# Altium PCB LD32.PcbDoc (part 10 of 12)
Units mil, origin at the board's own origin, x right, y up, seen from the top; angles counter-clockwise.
Board outline 7007.87 x 4368.85 mil, 12 copper layers (Top Layer, Int1 (GND), Int2 (AVDD), Int3 (DVDD), Int4 (GND), Int5 (ST), Int6 (SB), Int8 (AGND), Int7 (AVCC), Int9 (VCCA), Int10 (GND), Bottom Layer), stack 60.136 mil thick; 1165 components, 667 nets, 3910 pads, 2570 vias.
Unrouted connection lines stored in the file: 14.
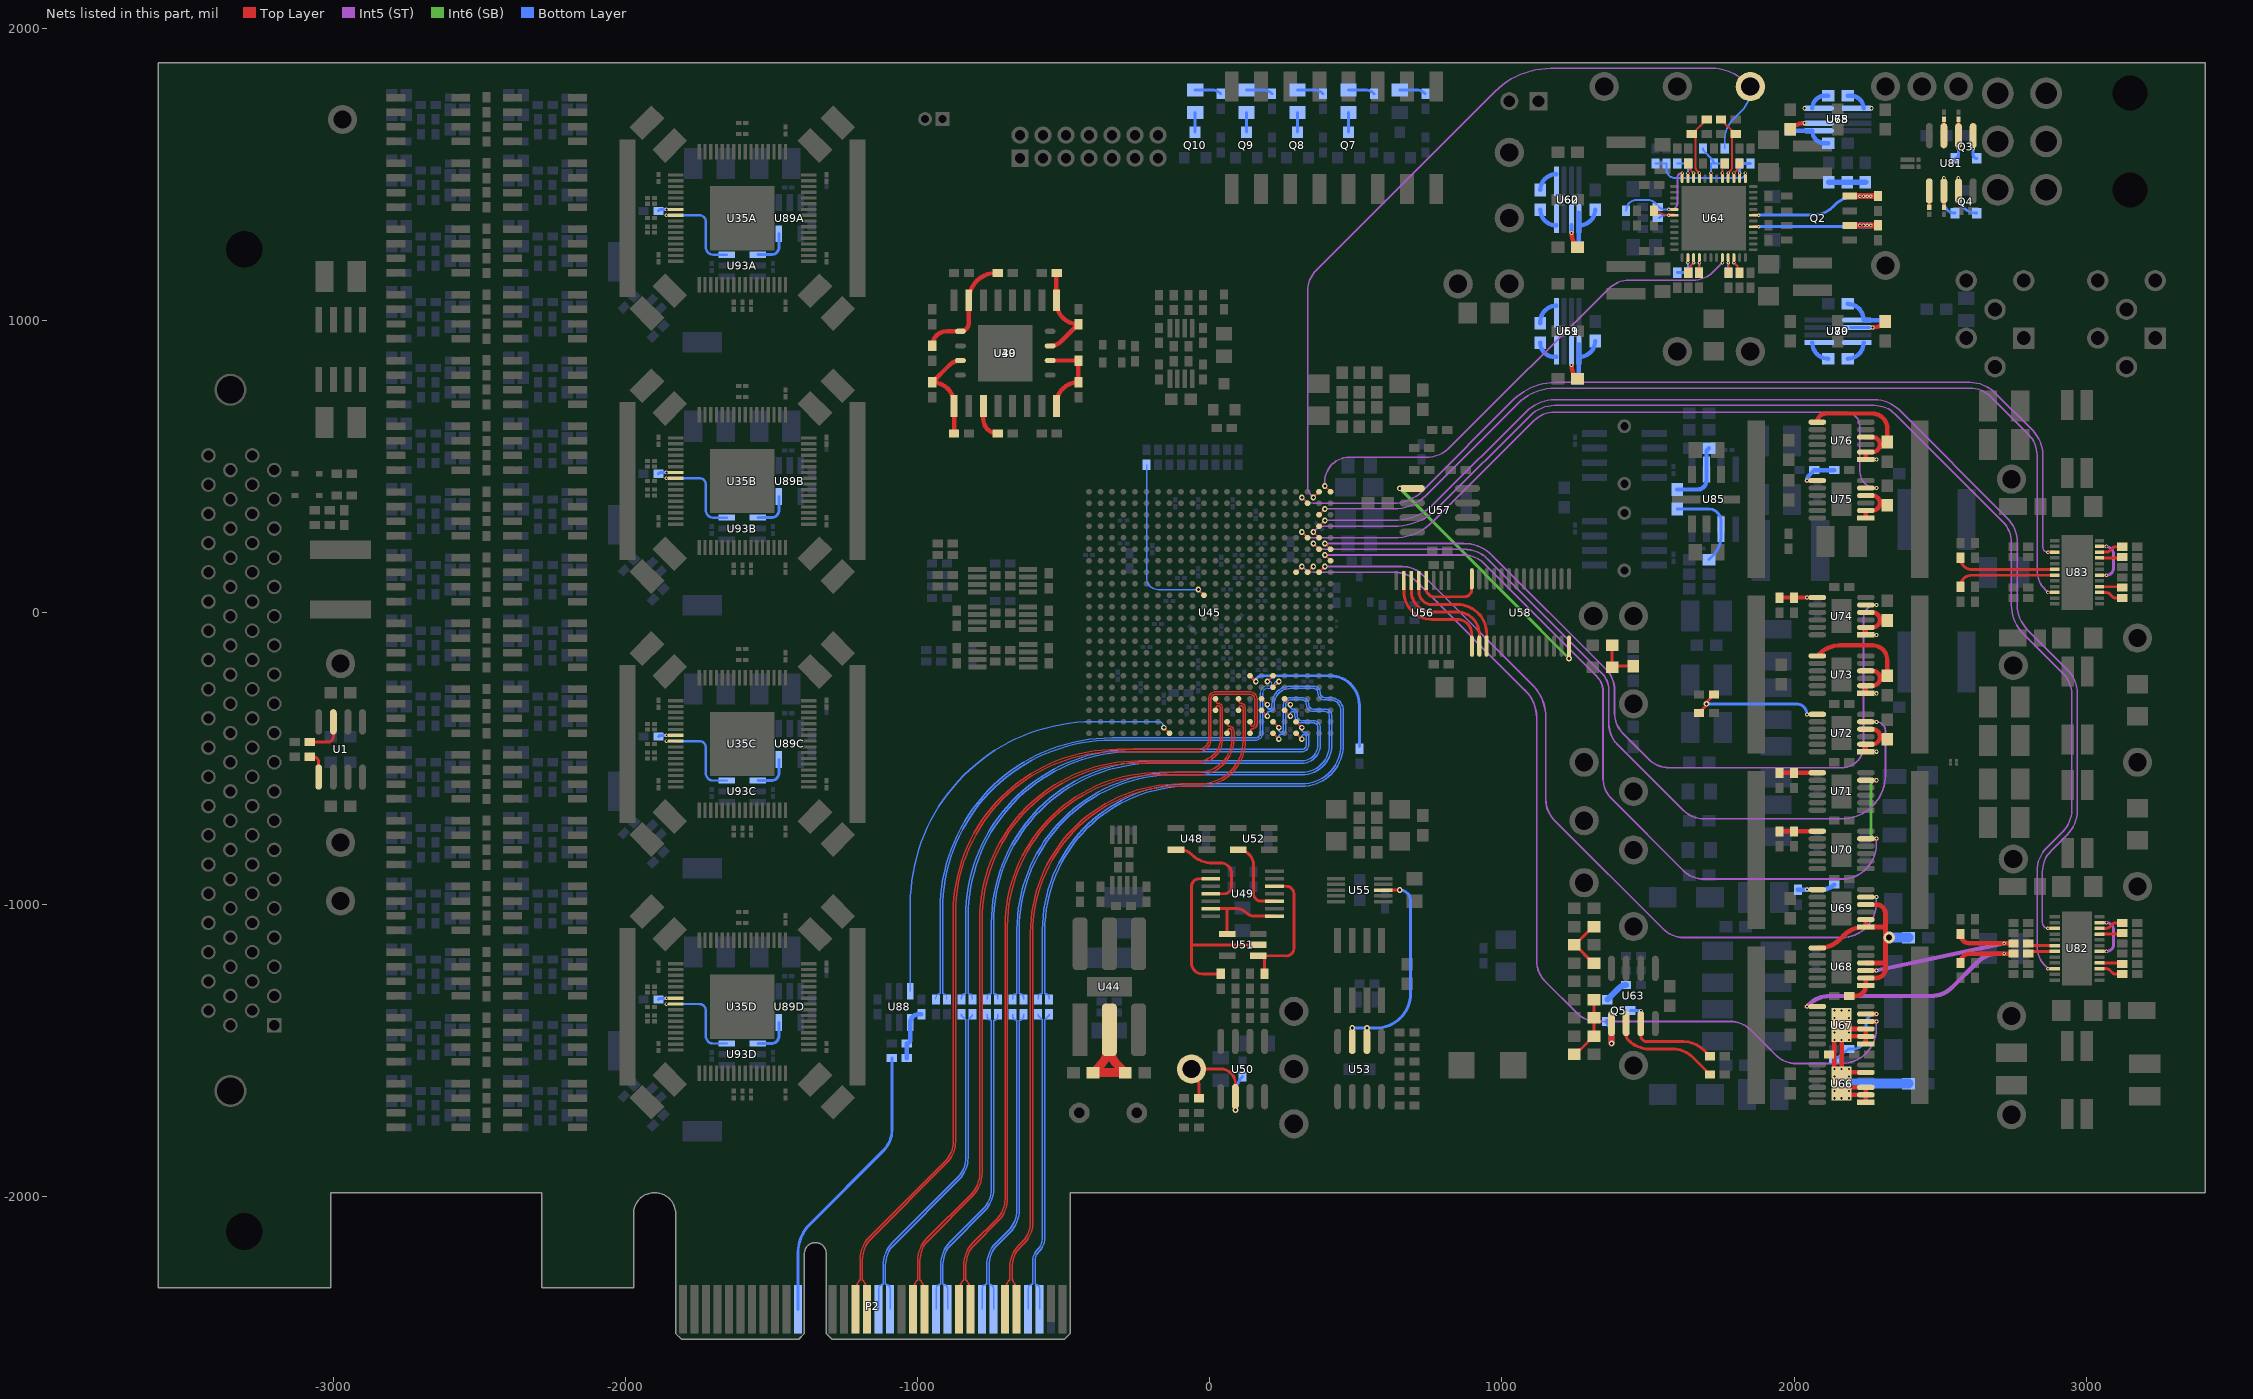
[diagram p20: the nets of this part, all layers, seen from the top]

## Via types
v1: diameter 12, hole 6, Top Layer to Bottom Layer, tented both sides, 1500 vias
v2: diameter 19, hole 10, Top Layer to Bottom Layer, tented both sides, 404 vias
v3: diameter 20, hole 10, Top Layer to Bottom Layer, tented both sides, 337 vias
v4: diameter 14, hole 7, Top Layer to Bottom Layer, tented both sides, 212 vias
v5: diameter 30, hole 15, Top Layer to Bottom Layer, tented both sides, 37 vias
v6: diameter 19.68, hole 7.87, Top Layer to Bottom Layer, 25 vias
v7: diameter 40, hole 20, Top Layer to Bottom Layer, tented both sides, 16 vias
v8: diameter 19.02, hole 10, Top Layer to Bottom Layer, tented both sides, 10 vias
v9: diameter 40, hole 20, Top Layer to Bottom Layer, 9 vias
v10: diameter 60, hole 40, Top Layer to Bottom Layer, 5 vias
v11: diameter 25, hole 13, Top Layer to Bottom Layer, 4 vias
v12: diameter 50, hole 25, Top Layer to Bottom Layer, tented both sides, 4 vias
v13: diameter 35, hole 20, Top Layer to Bottom Layer, 2 vias
v14: diameter 50, hole 25, Top Layer to Bottom Layer, 2 vias
v15: diameter 63, hole 45, Top Layer to Bottom Layer, 1 vias
v16: diameter 14.02, hole 7.01, Top Layer to Bottom Layer, tented both sides, 1 vias
v17: diameter 60, hole 40, Top Layer to Bottom Layer, tented both sides, 1 vias

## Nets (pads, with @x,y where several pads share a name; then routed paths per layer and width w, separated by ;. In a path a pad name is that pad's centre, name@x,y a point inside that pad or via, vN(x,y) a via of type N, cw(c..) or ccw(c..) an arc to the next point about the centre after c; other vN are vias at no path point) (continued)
NetDS2_2: DS2.2 R281.2 | length 90.9
  Bottom Layer w10: DS2.2@650,1788.39 706.61,1788.39 cw(c706.61,1744.7) R281.2@737.5,1775.59
NetDS3_1: DS3.1 Q7.3 | length 67.3
  Bottom Layer w10: Q7.3@475,1644.29 DS3.1@475,1711.61
NetDS3_2: DS3.2 R286.2 | length 90.9
  Bottom Layer w10: DS3.2@475,1788.39 531.61,1788.39 cw(c531.61,1744.7) R286.2@562.5,1775.59
NetDS4_1: DS4.1 Q8.3 | length 67.3
  Bottom Layer w10: Q8.3@300,1644.29 DS4.1@300,1711.61
NetDS4_2: DS4.2 R289.2 | length 90.9
  Bottom Layer w10: DS4.2@300,1788.39 356.61,1788.39 cw(c356.61,1744.7) R289.2@387.5,1775.59
NetDS5_1: DS5.1 Q9.3 | length 67.3
  Bottom Layer w10: Q9.3@125,1644.29 DS5.1@125,1711.61
NetDS5_2: DS5.2 R291.2 | length 90.9
  Bottom Layer w10: DS5.2@125,1788.39 181.61,1788.39 cw(c181.61,1744.7) R291.2@212.5,1775.59
NetDS6_1: DS6.1 Q10.3 | length 67.3
  Bottom Layer w10: Q10.3@-50,1644.29 DS6.1@-50,1711.61
NetDS6_2: DS6.2 R296.2 | length 90.9
  Bottom Layer w10: DS6.2@-50,1788.39 6.61,1788.39 cw(c6.61,1744.7) R296.2@37.5,1775.59
NetQ2_2: Q2.2 R187.1 U64.29 | length 513.9
  Top Layer w10: U64.29@1859.84,1320.47 v1(1878.54,1320.47)
  Top Layer w20: Q2.2@2190.16,1325 v1(2225,1325) v1(2237.5,1325) v1(2250,1325) v1(2262.5,1325) 2286.07,1325 ccw(c2286.07,1327.02) R187.1@2287.5,1325.59
  Bottom Layer w10: v1(1878.54,1320.47) 2226.57,1320.47 ccw(c2226.57,1335.93) v1(2237.5,1325)
  Bottom Layer w20: v1(2225,1325) v1(2237.5,1325) v1(2250,1325) v1(2262.5,1325)
NetQ2_4: Q2.4 R188.1 U64.31 | length 518.5
  Top Layer w10: U64.31@1859.84,1359.84 v1(1878.54,1359.84)
  Top Layer w20: Q2.4@2190.16,1425 v1(2225,1425) v1(2237.5,1425) v1(2250,1425) v1(2262.5,1425) 2286.07,1425 ccw(c2286.07,1427.02) R188.1@2287.5,1425.59
  Bottom Layer w10: v1(1878.54,1359.84) 2062.61,1359.84 ccw(c2062.61,1459.84) 2133.32,1389.13 2139.9,1395.71 cw(c2210.61,1325) 2210.61,1425 v1(2225,1425)
  Bottom Layer w20: v1(2225,1425) v1(2237.5,1425) v1(2250,1425) v1(2262.5,1425)
NetQ3_1: Q3.1 U81.1 | length 84.7
  Top Layer w10: v1(2612.5,1587.5) U81.1@2612.5,1631.99
  Bottom Layer w10: v1(2612.5,1587.5) 2612.5,1566.78 ccw(c2624.9,1566.78) Q3.1@2624.9,1554.38
NetQ3_2: Q3.2 R200.1 U81.2 | length 140.8
  Top Layer w10: v1(2562.5,1587.5) U81.2@2562.5,1631.99 R200.1@2562.5,1688.06
  Bottom Layer w10: Q3.2@2550.1,1554.38 ccw(c2550.1,1566.78) 2562.5,1566.78 v1(2562.5,1587.5)
NetQ4_1: Q4.1 U81.7 | length 200.7
  Top Layer w10: U81.7@2562.5,1443.01 v1(2562.5,1487.5)
  Bottom Layer w10: v1(2562.5,1487.5) 2562.5,1429.28 ccw(c2624.9,1429.28) Q4.1@2624.9,1366.88
NetQ4_2: Q4.2 R223.2 U81.6 | length 242.6
  Top Layer w10: R223.2@2512.5,1386.94 U81.6@2512.5,1443.01 v1(2512.5,1487.5)
  Bottom Layer w10: v1(2512.5,1487.5) 2512.5,1404.48 ccw(c2550.1,1404.48) Q4.2@2550.1,1366.88
NetQ5_1: Q5.1 U63.1 | length 147
  Top Layer w20: v8(1375,-1475) U63.1@1375,-1406.99
  Bottom Layer w20: Q5.1@1360.63,-1399.9 cw(c1325.94,-1434.59) 1375,-1434.59 v8(1375,-1475)
NetQ5_2: Q5.2 R274.1 | length 83.1
  Bottom Layer w20: Q5.2@1360.63,-1325.1 1401.05,-1284.67 cw(c1424.41,-1308.03) R274.1@1424.41,-1275
NetQ5_3: Q5.3 R247.2 U63.3 | length 342.4
  Top Layer w10: U63.3@1475,-1406.99 1475,-1450 ccw(c1490.09,-1450) 1479.42,-1460.67 1481.25,-1462.5 ccw(c1496.34,-1447.41) 1496.34,-1468.75 1620.49,-1468.75 cw(c1620.49,-1568.75) 1691.2,-1498.04 R247.2@1711.91,-1518.75
  Bottom Layer w10: Q5.3@1439.37,-1362.5 v1(1475.59,-1362.5)
NetR1_1: R1.1 U1.5 | length 92.1
  Top Layer w10: R1.1@-3080.66,-493.75 -3068.75,-493.75 cw(c-3068.75,-512.5) -3050,-512.5 U1.5@-3050,-563.24
NetR2_1: R2.1 U1.3 | length 142.2
  Top Layer w10: R2.1@-3080.66,-443.75 -3018.61,-443.75 ccw(c-3018.61,-425.14) -3000,-425.14 U1.3@-3000,-374.26
NetR67_1: R67.1 R72.1 U39.1 U40.7 | length 344
  Top Layer w15: R72.1@-875.59,612.5 -875,612.5 U39.1@-875,706.4 -875,713.09 ccw(c-950,713.09) R67.1@-950,788.09 -891.18,846.91 cw(c-853.54,809.28) U40.7@-853.54,862.5
NetR68_1: R68.1 R83.1 U39.15 U40.5 | length 400.1
  Top Layer w15: R68.1@-950,913.09 cw(c-900.59,913.09) -900.59,962.5 U40.5@-853.54,962.5 ccw(c-853.54,991.04) -825,991.04 U39.15@-825,1068.6 cw(c-731.1,1068.6) -731.1,1162.5 R83.1@-725.59,1162.5
NetR82_1: R82.1 U39.3 | length 122.1
  Top Layer w15: U39.3@-775,706.4 -775,661.91 ccw(c-725.59,661.91) R82.1@-725.59,612.5
NetR84_1: R84.1 R90.1 U39.9 U40.3 | length 344
  Top Layer w15: U40.3@-546.46,912.5 ccw(c-546.46,965.72) -508.82,928.09 R90.1@-450,986.91 cw(c-450,1061.91) -525,1061.91 U39.9@-525,1068.6 -525,1162.5 R84.1@-524.41,1162.5
NetR87_1: R87.1 R94.1 U44.2 | length 344.3
  Top Layer w30: R87.1@-399.61,-1574.8 -375.75,-1550.94 ccw(c-446.46,-1480.23) -346.46,-1480.23 -346.46,-1476.29 ccw(c-246.46,-1476.29) -317.17,-1547.01 R94.1@-289.37,-1574.8 R87.1@-399.61,-1574.8
NetR88_1: R88.1 R89.1 U39.8 U40.2 | length 295
  Top Layer w15: U40.2@-546.46,862.5 -450.59,862.5 R89.1@-450,861.91 R88.1@-450,788.09 ccw(c-450,713.09) -525,713.09 U39.8@-525,706.4
NetR102_1: R102.1 R292.2 TP4.1 U50.6 | length 451
  Top Layer w10: R102.1@-36.91,-1662.5 -36.91,-1624.28 ccw(c-124.28,-1624.28) TP4.1@-62.5,-1562.5 37.5,-1562.5 cw(c37.5,-1612.5) 87.5,-1612.5 U50.6@87.5,-1656.99
  Bottom Layer w10: v3(87.5,-1702.5) 87.5,-1648.45 cw(c172.86,-1648.45) R292.2@112.5,-1588.09
NetR108_1: R108.1 U49.9 U51.2 | length 692.4
  Top Layer w10: U49.9@3.25,-911.32 -36.32,-911.32 ccw(c-36.32,-937.5) -62.5,-937.5 -62.5,-1137.5 ; R108.1@37.5,-1236.91 -25.59,-1236.91 cw(c-25.59,-1200) -62.5,-1200 -62.5,-1137.5 ; U51.2@165.65,-1137.5 -62.5,-1137.5
NetR113_1: R113.1 U49.5 U51.1 | length 466.1
  Top Layer w10: U51.1@165.65,-1174.9 U51.1@187.5,-1174.9 ; R113.1@187.5,-1236.91 U51.1@187.5,-1174.9 ; U49.5@221.75,-936.91 261.91,-936.91 cw(c261.91,-962.5) 287.5,-962.5 287.5,-1150 cw(c262.5,-1150) 262.5,-1175 262.5,-1174.9 U51.1@187.5,-1174.9
NetR122_1: R122.1 U59.6 U61.6 | length 52.6
  Top Layer w15: v4(1237.8,846.76) ccw(c1300.78,846.76) 1256.24,802.23 R122.1@1258.46,800
NetR123_2: R123.2 R124.1 U59.5 U61.5 | length 206.8
  Bottom Layer w15: R123.2@1258.46,800 ccw(c1246.58,811.88) 1263.39,811.88 U61.5@1263.39,919.17 ; U59.5@1263.39,874.9 1264.62,874.9 ccw(c1264.62,929.04) R124.1@1318.75,929.04
NetR125_1: R125.1 R127.2 U60.5 U62.5 | length 206.8
  Bottom Layer w15: R127.2@1258.46,1250 ccw(c1246.58,1261.88) 1263.39,1261.88 U62.5@1263.39,1369.17 ; U60.5@1263.39,1324.9 1264.62,1324.9 ccw(c1264.62,1379.04) R125.1@1318.75,1379.04
NetR126_1: R126.1 U60.6 U62.6 | length 80.5
  Top Layer w15: v4(1237.8,1299.5) ccw(c1307.4,1299.5) 1258.18,1250.28 R126.1@1258.46,1250
  Bottom Layer w15: v4(1237.8,1299.5) U60.6@1237.8,1324.9
NetR130_1: R130.1 R131.1 R136.2 R140.1 | length 217
  Top Layer w10: R140.1@1248.75,-1510 1260.94,-1497.81 1266.9,-1497.81 1298.06,-1466.65 1298.06,-1464.69 1312.75,-1450 R136.2@1314.71,-1450 R130.1@1314.71,-1387.5 R131.1@1314.71,-1325
NetR133_1: R133.1 R134.2 R135.1 | length 180.5
  Top Layer w10: R134.2@1247.79,-1137.5 ccw(c1247.79,-1133.32) 1250.74,-1136.28 1310.11,-1076.91 cw(c1314.71,-1081.52) R135.1@1314.71,-1075 ; R134.2@1251.57,-1139.07 1310.94,-1198.44 ccw(c1314.71,-1194.65) R133.1@1314.71,-1200
NetR137_1: R137.1 R138.2 R139.1 | length 148.9
  Top Layer w10: R139.1@1377.21,-112.5 R137.1@1377.21,-187.5 cw(c1386.96,-197.24) 1386.96,-183.46 R138.2@1450,-183.46
NetR141_1: R141.1 U59.8 U61.8 | length 82.7
  Bottom Layer w15: R141.1@1131.25,922.79 ccw(c1179.13,922.79) 1179.13,874.9 U59.8@1186.61,874.9
NetR141_2: R141.2 U59.1 U61.1 | length 92
  Bottom Layer w15: R141.2@1131.25,989.71 1131.25,994.73 cw(c1186.61,994.73) U59.1@1186.61,1050.1
NetR142_1: R142.1 U60.8 U62.8 | length 86.3
  Bottom Layer w15: R142.1@1131.25,1379.04 ccw(c1185.38,1379.04) 1185.38,1324.9 U60.8@1186.61,1324.9
NetR142_2: R142.2 U60.1 U62.1 | length 86.3
  Bottom Layer w15: R142.2@1131.25,1445.96 cw(c1185.38,1445.96) 1185.38,1500.1 U60.1@1186.61,1500.1
NetR143_2: R143.2 U63.2 | length 381.2
  Top Layer w10: U63.2@1425,-1450 U63.2@1425,-1447.13 ; U63.2@1425,-1406.99 U63.2@1425,-1447.13 ; R143.2@1711.91,-1581.25 1653.7,-1523.04 ccw(c1582.99,-1593.75) 1582.99,-1493.75 1504.04,-1493.75 cw(c1504.04,-1393.75) 1433.33,-1464.46 1431.37,-1462.5 cw(c1446.74,-1447.13) U63.2@1425,-1447.13
NetR144_1: R144.1 R269.1 U64.6 | length 112.6
  Top Layer w7: R144.1@1520,1383.46 1524.26,1379.2 ccw(c1571,1425.94) v1(1571,1359.84)
  Top Layer w10: v1(1571,1359.84) U64.6@1590.16,1359.84
  Bottom Layer w7: R269.1@1538.09,1350 cw(c1561.85,1326.24) 1561.85,1359.84 v1(1571,1359.84)
NetR145_2: R145.2 U64.15 | length 58.1
  Top Layer w7: R145.2@1637.5,1163.09 cw(c1675.33,1163.09) 1648.58,1189.84 v1(1656.1,1197.36)
  Top Layer w10: v1(1656.1,1197.36) U64.15@1656.1,1215.16
NetR146_2: R146.2 U64.46 | length 58.3
  Top Layer w7: R146.2@1637.5,1536.91 ccw(c1671.95,1536.91) 1647.59,1512.55 v1(1656.1,1504.04)
  Top Layer w10: U64.46@1656.1,1484.84 v1(1656.1,1504.04)
NetR147_1: R147.1 R148.1 U64.45 | length 229.1
  Top Layer w7: R148.1@1649.41,1637.5 ccw(c1649.41,1640.35) 1651.42,1638.33 R147.1@1700.59,1687.5 ; R148.1@1662.5,1637.5 1662.5,1525 ccw(c1681.03,1525) 1667.93,1511.89 v1(1675.79,1504.04)
  Top Layer w10: U64.45@1675.79,1484.84 v1(1675.79,1504.04)
NetR149_1: R149.1 R150.2 U72.7 | length 482.5
  Top Layer w10: R149.1@1674.41,-343.75 1696,-322.16 ccw(c1686.34,-312.5) v3(1700,-312.5) cw(c1713.66,-312.5) 1704,-302.84 R150.2@1725.59,-281.25 ; v4(2043.75,-348.52) U72.7@2079.44,-348.52
  Bottom Layer w10: v3(1700,-312.5) 2007.73,-312.5 cw(c2007.73,-348.52) v4(2043.75,-348.52)
NetR151_1: R151.1 R152.2 U75.7 | length 148.8
  Top Layer w15: v4(2043.75,451.48) U75.7@2079.44,451.48
  Bottom Layer w15: v4(2043.75,451.48) cw(c2068.94,451.48) 2051.12,469.28 R152.2@2069.34,487.5 R151.1@2136.91,487.5
NetR153_1: R153.1 R261.1 U64.16 | length 87
  Top Layer w7: R153.1@1675,1163.09 1675,1214.37 cw(c1675.79,1214.37) U64.16@1675.79,1215.16
  Bottom Layer w7: R261.1@1675,1163.09 ccw(c1673.1,1164.99) 1675.79,1164.99 v1(1675.79,1197.36)
NetR154_1: R154.1 R155.1 U64.40 | length 229.1
  Top Layer w7: R155.1@1749.41,1687.5 1798.57,1638.34 ccw(c1800.59,1640.35) R154.1@1800.59,1637.5 ; v1(1774.21,1504.04) 1782.07,1511.89 ccw(c1768.97,1525) 1787.5,1525 R154.1@1787.5,1637.5
  Top Layer w10: U64.40@1774.21,1484.84 v1(1774.21,1504.04)
NetR156_1: R156.1 U64.41 | length 54.2
  Top Layer w7: v1(1754.53,1504.04) 1754.53,1517.66 cw(c1781.75,1517.66) R156.1@1762.5,1536.91
  Top Layer w10: U64.41@1754.53,1484.84 v1(1754.53,1504.04)
NetR157_1: R157.1 R251.1 U64.21 | length 87
  Top Layer w7: U64.21@1774.21,1215.16 cw(c1774.21,1214.37) 1775,1214.37 R157.1@1775,1163.09
  Bottom Layer w7: v1(1774.21,1197.36) 1774.21,1164.99 ccw(c1776.9,1164.99) R251.1@1775,1163.09
NetR158_2: R158.2 U64.22 | length 58.1
  Top Layer w7: v1(1793.9,1197.36) 1801.42,1189.84 cw(c1774.67,1163.09) R158.2@1812.5,1163.09
  Top Layer w10: v1(1793.9,1197.36) U64.22@1793.9,1215.16
NetR159_2: R159.2 U64.39 | length 58.3
  Top Layer w7: v1(1793.9,1504.04) 1802.41,1512.55 ; 1802.42,1512.56 ccw(c1778.05,1536.91) R159.2@1812.5,1536.91
  Top Layer w10: U64.39@1793.9,1484.84 v1(1793.9,1504.04)
NetR161_1: R161.1 U65.6 U78.6 | length 53.8
  Top Layer w15: R161.1@1987.5,1654.04 1988.76,1655.3 cw(c2035.61,1608.45) v4(2035.61,1674.7)
NetR162_1: R162.1 R170.2 U70.7 | length 129.9
  Top Layer w16: R162.1@1950,-749.41 cw(c1950.89,-749.41) 1950.89,-748.52 U70.7@2079.44,-748.52
NetR163_1: R163.1 R171.2 U71.7 | length 129.9
  Top Layer w16: R163.1@1950,-549.41 cw(c1950.89,-549.41) 1950.89,-548.52 U71.7@2079.44,-548.52
NetR164_2: R164.2 R172.1 U74.7 | length 129.7
  Top Layer w15: R164.2@1950,50.59 cw(c1952.14,48.45) 1952.14,51.48 v4(2043.75,51.48) U74.7@2079.44,51.48
NetR169_2: R169.2 R176.1 U65.5 U78.5 | length 156.8
  Bottom Layer w15: R169.2@1987.5,1654.04 ccw(c1992.42,1654.04) 1992.42,1649.11 U65.5@2062.4,1649.11 2062.4,1647.88 ccw(c2104.04,1647.88) 2104.04,1606.25 R176.1@2116.54,1606.25
NetR174_1: R174.1 R225.1 U66.1 U66.2 U66.3 U66.5 U66.13 U67.1 U67.2 U67.3 U67.13 | length 1001.9
  Top Layer w15: v4(2137.5,-1562.2) v4(2137.5,-1462.5) ; v4(2162.5,-1562.5) ccw(c2174.11,-1562.5) 2174.11,-1574.11 U66.5@2245.56,-1574.11
  Top Layer w16: v4(2162.5,-1662.5) 2162.5,-1650.89 U66.2@2245.56,-1650.89 ; v9(2162.5,-1612.5) 2162.5,-1625.3 U66.3@2245.56,-1625.3 U66.2@2245.56,-1650.89 ; v4(2162.5,-1562.5) v4(2162.5,-1462.5) 2162.5,-1450.89 U67.2@2245.56,-1450.89 ; v9(2162.5,-1412.5) 2162.5,-1425.3 U67.3@2245.56,-1425.3 U67.2@2245.56,-1450.89 ; U66.1@2245.56,-1676.48 U66.2@2245.56,-1650.89 ; U67.1@2245.56,-1476.48 U67.2@2245.56,-1450.89
  Bottom Layer w35: v9(2162.5,-1612.5) R225.1@2391.54,-1612.5
  other v4: 2137.5,-1662.5 2187.5,-1662.5 2137.5,-1637.5 2187.5,-1637.5 2137.5,-1587.5 2187.5,-1587.5 2187.5,-1562.5 2187.5,-1462.5 2137.5,-1437.5 2187.5,-1437.5 2137.5,-1387.5 2187.5,-1387.5 2137.5,-1362.5 2162.5,-1362.5 2187.5,-1362.5
NetR175_1: R175.1 U65.8 U78.8 | length 79.8
  Bottom Layer w15: U65.8@2062.4,1727.12 U65.8@2062.4,1725.89 cw(c2105.27,1725.89) 2105.27,1768.75 R175.1@2116.54,1768.75
  other v4: 2035.61,1725.89
NetR175_2: R175.2 U65.1 U78.1 | length 79.8
  Bottom Layer w10: U65.1@2237.6,1725.89 U65.1@2237.6,1727.12
  Bottom Layer w15: R175.2@2183.46,1768.75 2194.73,1768.75 cw(c2194.73,1725.89) U65.1@2237.6,1725.89
  other v4: 2264.86,1725.89
NetR180_2: R180.2 R226.1 U68.1 U68.2 U68.4 U68.7 U69.1 U69.2 U69.4 | length 875.2
  Top Layer w16: U68.7@2079.44,-1148.52 2085.06,-1148.52 ccw(c2085.06,-1048.52) 2155.77,-1119.23 2169.23,-1105.77 cw(c2239.95,-1176.48) 2239.95,-1076.48 U69.1@2245.56,-1076.48 ; R180.2@2188.09,-1312.5 2209.54,-1312.5 ccw(c2209.54,-1276.48) U68.1@2245.56,-1276.48 U68.2@2245.56,-1250.89 2281.25,-1250.89 2281.25,-1250.59 ccw(c2281.25,-1219.34) 2312.5,-1219.34 2312.5,-1199.7 ; U68.4@2245.56,-1199.7 2312.5,-1199.7 ; U69.2@2245.56,-1050.89 U69.1@2245.56,-1076.48 ; U69.4@2245.56,-999.7 2281.25,-999.7 cw(c2281.25,-1030.95) 2312.5,-1030.95 2312.5,-1076.48 ; U69.1@2245.56,-1076.48 2312.5,-1076.48 ; 2312.5,-1199.7 2312.5,-1076.48
  Bottom Layer w35: v7(2325,-1112.5) R226.1@2391.54,-1112.5
NetR184_1: R184.1 U79.8 U80.8 | length 86.3
  Bottom Layer w15: R184.1@2183.46,868.75 ccw(c2183.46,922.88) 2237.6,922.88 U79.8@2237.6,924.11
NetR184_2: R184.2 U79.1 U80.1 | length 86.3
  Bottom Layer w15: U79.1@2062.4,924.11 2062.4,922.88 ccw(c2116.54,922.88) R184.2@2116.54,868.75
NetR185_1: R185.1 R195.2 U79.5 U80.5 | length 171.7
  Bottom Layer w15: R185.1@2183.46,1056.25 cw(c2183.46,1002.12) 2237.6,1002.12 U79.5@2237.6,1000.89 2307.58,1000.89 cw(c2307.58,995.96) R195.2@2312.5,995.96 ; R195.2@2313.83,1000.89 cw(c2313.83,995.96) R195.2@2318.75,995.96
NetR190_1: R190.1 U72.1 U72.2 U72.4 | length 178.5
  Top Layer w15: U72.1@2245.56,-476.48 U72.2@2245.56,-450.89 2267.53,-450.89 ccw(c2267.53,-424.66) 2293.75,-424.66 ; U72.4@2245.56,-399.7 2268.79,-399.7 cw(c2268.79,-424.66) 2293.75,-424.66 ; R190.1@2318.75,-433.46 ccw(c2297.5,-454.72) 2297.5,-424.66 2293.75,-424.66
  other v4: 2281.54,-476.48
NetR191_1: R191.1 U73.1 U73.2 U73.4 U73.7 | length 507.4
  Top Layer w15: U73.7@2079.44,-148.52 2086.17,-141.79 cw(c2156.88,-212.5) 2156.88,-112.5 2268.79,-112.5 cw(c2268.79,-161.91) 2318.2,-161.91 R191.1@2318.2,-216.54 ; U73.1@2245.56,-276.48 U73.2@2245.56,-250.89 2267.53,-250.89 ccw(c2267.53,-224.66) 2293.75,-224.66 ccw(c2268.79,-224.66) 2268.79,-199.7 U73.4@2245.56,-199.7 ; 2297.05,-225.3 cw(c2318.2,-246.44) R191.1@2318.2,-216.54 ; R191.1@2318.75,-216.54 R191.1@2318.2,-216.54
  other v4: 2281.25,-276.48
NetR192_1: R192.1 U74.1 U74.2 U74.4 | length 176.7
  Top Layer w15: U74.1@2245.56,-76.48 U74.2@2245.56,-50.89 2268.16,-50.89 ccw(c2268.16,-25.3) 2293.75,-25.3 ; U74.4@2245.56,0.3 2268.16,0.3 cw(c2268.16,-25.3) 2293.75,-25.3 ; R192.1@2318.75,-27.21 ccw(c2314.12,-31.85) 2314.12,-25.3 2293.75,-25.3
  other v4: 2281.25,-76.48
NetR193_1: R193.1 U75.1 U75.2 U75.4 | length 178.4
  Top Layer w15: U75.1@2245.56,323.52 U75.2@2245.56,349.11 2268.16,349.11 ccw(c2268.16,374.7) 2293.75,374.7 ; U75.4@2245.56,400.3 2268.16,400.3 cw(c2268.16,374.7) 2293.75,374.7 ; R193.1@2318.75,366.54 ccw(c2299.03,346.81) 2299.03,374.7 2293.75,374.7
NetR194_1: R194.1 U76.1 U76.2 U76.4 U76.7 | length 513.1
  Top Layer w15: U76.7@2079.44,651.48 cw(c2109.21,651.48) 2109.21,681.25 2267.56,681.25 cw(c2267.56,630.06) 2318.75,630.06 R194.1@2318.75,583.46 cw(c2310.29,583.46) 2310.29,575 2293.75,575 ; U76.1@2245.56,523.52 U76.2@2245.56,549.11 2267.86,549.11 ccw(c2267.86,575) 2293.75,575 ; U76.4@2245.56,600.3 2268.45,600.3 cw(c2268.45,575) 2293.75,575
  other v4: 2281.25,523.52
NetR196_1: R196.1 U79.6 U80.6 | length 125.7
  Top Layer w15: R196.1@2312.5,995.96 2308.35,991.82 cw(c2268.45,1031.73) v4@2268.85,975.3 ; v4@2268.85,975.3 cw(c2268.45,1031.73) v4(2268.45,975.3) v4@2268.85,975.3
  Bottom Layer w10: U80.6@2193.33,975.3 U79.6@2237.6,975.3 v4(2268.45,975.3)
NetR197_1: R197.1 U81.3 | length 56.1
  Top Layer w10: U81.3@2512.5,1631.99 R197.1@2512.5,1688.06
NetR198_2: R198.2 U81.5 | length 56.1
  Top Layer w10: R198.2@2462.5,1386.94 U81.5@2462.5,1443.01
NetR201_2: R201.2 R207.1 U67.7 | length 972.9
  Top Layer w15: v4(2043.75,-1348.52) U67.7@2079.44,-1348.52 ; R201.2@2568.75,-1199.41 cw(c2600.66,-1199.41) 2600.66,-1167.5 v1(2718.75,-1167.5) R207.1@2750.66,-1167.5
  Int5 (ST) w15: v4(2043.75,-1348.52) 2050.48,-1341.79 cw(c2121.2,-1412.5) 2121.2,-1312.5 2469.83,-1312.5 ccw(c2469.83,-1212.5) 2540.54,-1283.21 2626.96,-1196.79 cw(c2697.67,-1267.5) 2697.67,-1167.5 v1(2718.75,-1167.5)
NetR202_1: R202.1 R208.1 U68.3 | length 683
  Top Layer w15: U68.3@2245.56,-1225.3 v4(2281.25,-1225.3) ; R202.1@2568.75,-1100.59 ccw(c2600.66,-1100.59) 2600.66,-1132.5 v1(2718.75,-1132.5) R208.1@2750.66,-1132.5
  Int5 (ST) w15: v4(2281.25,-1225.3) v1(2718.75,-1132.5)
NetR203_2: R203.2 U83.7 | length 346.1
  Top Layer w10: R203.2@2568.75,88.09 cw(c2608.32,88.09) 2608.32,127.66 U83.7@2892.25,127.66
NetR204_1: R204.1 U83.6 | length 346.1
  Top Layer w10: R204.1@2568.75,186.91 ccw(c2608.32,186.91) 2608.32,147.34 U83.6@2892.25,147.34
NetR207_2: R207.2 U82.7 | length 94.8
  Top Layer w10: R207.2@2801.84,-1167.5 cw(c2809.5,-1167.5) 2809.5,-1159.84 U82.7@2892.25,-1159.84
NetR208_2: R208.2 U82.6 | length 94.8
  Top Layer w10: R208.2@2801.84,-1132.5 ccw(c2809.5,-1132.5) 2809.5,-1140.16 U82.6@2892.25,-1140.16
NetR211_2: R211.2 U82.21 | length 78.8
  Top Layer w10: U82.21@3045.25,-1100.79 3115.22,-1100.79 ccw(c3115.22,-1089.56) R211.2@3123.16,-1097.5
NetR212_2: R212.2 U83.21 | length 78.8
  Top Layer w10: U83.21@3045.25,186.71 3115.22,186.71 ccw(c3115.22,197.94) R212.2@3123.16,190
NetR213_1: R213.1 U82.15 | length 84.1
  Top Layer w10: U82.15@3045.25,-1218.9 3066.52,-1218.9 cw(c3066.52,-1239.73) 3081.25,-1225 3089.79,-1233.54 ccw(c3099.36,-1223.96) 3099.36,-1237.5 R213.1@3123.16,-1237.5
NetR214_1: R214.1 U82.16 | length 78.8
  Top Layer w10: U82.16@3045.25,-1199.21 3115.22,-1199.21 cw(c3115.22,-1210.44) R214.1@3123.16,-1202.5
NetR215_1: R215.1 U82.22 | length 84.1
  Top Layer w10: U82.22@3045.25,-1081.1 3066.52,-1081.1 ccw(c3066.52,-1060.27) 3081.25,-1075 3089.79,-1066.46 cw(c3099.36,-1076.04) 3099.36,-1062.5 R215.1@3123.16,-1062.5
NetR216_1: R216.1 U83.15 | length 84.1
  Top Layer w10: U83.15@3045.25,68.6 3066.52,68.6 cw(c3066.52,47.77) 3081.25,62.5 3089.79,53.96 ccw(c3099.36,63.54) 3099.36,50 R216.1@3123.16,50
NetR217_1: R217.1 U83.16 | length 78.8
  Top Layer w10: U83.16@3045.25,88.29 3115.22,88.29 cw(c3115.22,77.06) R217.1@3123.16,85
NetR218_1: R218.1 U83.22 | length 84.1
  Top Layer w10: U83.22@3045.25,206.4 3066.52,206.4 ccw(c3066.52,227.23) 3081.25,212.5 3089.79,221.04 cw(c3099.36,211.46) 3099.36,225 R218.1@3123.16,225
NetR229_2: R229.2 R230.1 R235.1 | length 125
  Bottom Layer w20: R235.1@2118.75,1472.79 R229.2@2243.75,1472.79
NetR232_1: R232.1 R233.2 U67.5 | length 277.8
  Top Layer w16: U67.5@2245.56,-1374.11 v4(2281.25,-1374.11)
  Bottom Layer w10: R232.1@2136.91,-1531.25 2149.63,-1522.47 2175.37,-1502.53 R233.2@2188.09,-1493.75 2201.76,-1493.75 ccw(c2201.76,-1450) 2245.51,-1450 2245.51,-1409.85 cw(c2281.25,-1409.85) v4(2281.25,-1374.11)
NetR234_1: R234.1 R236.2 U69.7 | length 129.5
  Bottom Layer w16: R236.2@2012.5,-949.41 cw(c2013.39,-949.41) 2013.39,-948.52 v4(2043.75,-948.52) 2095.21,-948.52 ccw(c2095.21,-889.55) R234.1@2136.91,-931.25
NetR243_1: R243.1 R244.2 U85.2 | length 317.9
  Bottom Layer w10: R244.2@1600,354.04 1708.46,354.04 cw(c1708.46,312.5) 1750,312.5 U85.2@1750,285.14 1750,264.21 cw(c1650,264.21) 1720.71,193.5 R243.1@1708.46,181.25
NetR244_1: R244.1 R262.2 U85.6 | length 231.7
  Bottom Layer w15: R244.1@1600,420.96 1669,420.96 ccw(c1669,451.96) 1700,451.96 U85.6@1700,489.86 1700,554.04 R262.2@1708.46,562.5
NetR246_2: R246.2 R250.1 U64.38 | length 89.9
  Top Layer w10: U64.38@1813.58,1484.84 v1(1813.58,1504.04)
  Bottom Layer w10: v1(1813.58,1504.04) 1813.58,1534.3 ccw(c1809.89,1534.3) R250.1@1812.5,1536.91 R246.2@1850,1536.91
NetR252_1: R252.1 R256.1 R260.1 U64.43 | length 177.7
  Top Layer w10: U64.43@1715.16,1484.84 v1(1715.16,1504.04)
  Bottom Layer w7: R260.1@1687.5,1588.09 ccw(c1698.69,1588.09) 1690.78,1580.18 1718.6,1552.35 cw(c1703.16,1536.91) R256.1@1725,1536.91 ; v1(1715.16,1504.04) 1715.16,1536.91 R256.1@1725,1536.91 ; R256.1@1720.15,1548.61 cw(c1708.46,1536.91) R256.1@1725,1536.91 ; R252.1@1762.5,1536.91 R256.1@1725,1536.91
NetR263_1: R263.1 R265.2 U64.14 | length 90.2
  Top Layer w10: v1(1636.42,1197.36) U64.14@1636.42,1215.16
  Bottom Layer w7: v1(1636.42,1197.36) 1636.42,1164.17 ccw(c1637.5,1164.17) R263.1@1637.5,1163.09
  Bottom Layer w10: R265.2@1600,1163.09 R263.1@1637.5,1163.09
NetR264_1: R264.1 R266.2 U64.47 | length 89.9
  Top Layer w10: U64.47@1636.42,1484.84 v1(1636.42,1504.04)
  Bottom Layer w7: R266.2@1600,1536.91 R264.1@1637.5,1536.91 ccw(c1640.11,1534.3) 1636.42,1534.3 v1(1636.42,1504.04)
NetR267_2: R267.2 R271.1 U64.37 | length 373.7
  Top Layer w7: U64.37@1833.27,1484.84 v1(1833.27,1504.04)
  Bottom Layer w7: R271.1@1525,1536.91 R267.2@1562.5,1536.91 1562.5,1517.5 ccw(c1592.69,1517.5) 1592.69,1487.3 1816.54,1487.3 ccw(c1816.54,1504.04) v1(1833.27,1504.04)
NetR268_2: R268.2 R278.1 U64.5 U64.48 | length 370.8
  Top Layer w10: v1(1571,1379.53) U64.5@1590.16,1379.53 ; U64.48@1616.73,1484.84 v1(1616.73,1504.04)
  Int5 (ST) w7: v1(1571,1379.53) 1579.53,1379.53 ccw(c1579.53,1400) 1600,1400 1600,1487.3 cw(c1616.73,1487.3) v1(1616.73,1504.04)
  Bottom Layer w7: R278.1@1425,1375.59 cw(c1461.91,1375.59) 1461.91,1412.5 1500,1412.5 cw(c1500,1380.9) 1522.35,1403.24 1538.09,1387.5 ccw(c1557.34,1406.75) 1557.34,1379.53 v1(1571,1379.53)
NetR287_1: R287.1 U45.F8 | length 592.6
  Top Layer w10: U45.F8@137.8,-216.54 v2(157.48,-236.22)
  Bottom Layer w10: v2(157.48,-236.22) cw(c177.17,-236.22) 177.17,-216.54 411.81,-216.54 cw(c411.81,-316.54) 511.81,-316.54 R287.1@511.81,-458.66
NetR316_2: R316.2 R317.2 R318.1 U88.4 | length 181.9
  Bottom Layer w15: R317.2@-1036.91,-1525 R318.1@-1036.91,-1475 ccw(c-1036.91,-1463.19) -1025.1,-1463.19 U88.4@-1025.1,-1403.15 cw(c-997.54,-1403.15) -997.54,-1375.59 R316.2@-987.5,-1375.59
NetR327A_2: R327A.2 U35A.23 | length 61.3
  Top Layer w10: v1(-1860,1379.53) U35A.23@-1827.5,1379.53
  Bottom Layer w10: R327A.2@-1886.91,1375 -1882.38,1379.53 v1(-1860,1379.53)
NetR327B_2: R327B.2 U35B.23 | length 61.3
  Top Layer w10: v1(-1860,479.53) U35B.23@-1827.5,479.53
  Bottom Layer w10: R327B.2@-1886.91,475 -1882.38,479.53 v1(-1860,479.53)
NetR327C_2: R327C.2 U35C.23 | length 61.3
  Top Layer w10: v1(-1860,-420.47) U35C.23@-1827.5,-420.47
  Bottom Layer w10: R327C.2@-1886.91,-425 -1882.38,-420.47 v1(-1860,-420.47)
NetR327D_2: R327D.2 U35D.23 | length 61.3
  Top Layer w10: v1(-1860,-1320.47) U35D.23@-1827.5,-1320.47
  Bottom Layer w10: R327D.2@-1886.91,-1325 -1882.38,-1320.47 v1(-1860,-1320.47)
NetU35A_24: U35A.24 U93A.3 | length 353.9
  Top Layer w8: v1(-1860,1359.84) U35A.24@-1827.5,1359.84
  Bottom Layer w8: v1(-1860,1359.84) -1747.34,1359.84 cw(c-1747.34,1337.5) -1725,1337.5 -1725,1250 ccw(c-1699.9,1250) -1699.9,1224.9 U93A.3@-1653.15,1224.9
NetU35B_24: U35B.24 U93B.3 | length 353.9
  Top Layer w8: v1(-1860,459.84) U35B.24@-1827.5,459.84
  Bottom Layer w8: v1(-1860,459.84) -1747.34,459.84 cw(c-1747.34,437.5) -1725,437.5 -1725,350 ccw(c-1699.9,350) -1699.9,324.9 U93B.3@-1653.15,324.9
NetU35C_24: U35C.24 U93C.3 | length 353.9
  Top Layer w8: v1(-1860,-440.16) U35C.24@-1827.5,-440.16
  Bottom Layer w8: v1(-1860,-440.16) -1747.34,-440.16 cw(c-1747.34,-462.5) -1725,-462.5 -1725,-550 ccw(c-1699.9,-550) -1699.9,-575.1 U93C.3@-1653.15,-575.1
NetU35D_24: U35D.24 U93D.3 | length 353.9
  Top Layer w8: v1(-1860,-1340.16) U35D.24@-1827.5,-1340.16
  Bottom Layer w8: v1(-1860,-1340.16) -1747.34,-1340.16 cw(c-1747.34,-1362.5) -1725,-1362.5 -1725,-1450 ccw(c-1699.9,-1450) -1699.9,-1475.1 U93D.3@-1653.15,-1475.1
NetU48_5: U48.5 U49.11 | length 352.4
  Top Layer w10: U48.5@-115.65,-812.4 -99.71,-812.4 cw(c-99.71,-865.03) -62.5,-827.81 -62.1,-828.21 ccw(c8.61,-757.5) 8.61,-857.5 37.5,-857.5 cw(c37.5,-894.8) 74.8,-894.8 74.8,-937.5 cw(c49.8,-937.5) 49.8,-962.5 U49.11@3.25,-962.5
NetU49_1: U49.1 U49.13 U51.4 | length 312.4
  Top Layer w10: U49.13@3.25,-1013.68 61.56,-1013.68 ; U51.4@59.35,-1100.1 59.35,-1019 cw(c66.88,-1019) 61.56,-1013.68 ; U49.1@221.75,-1039.27 152.38,-1039.27 cw(c152.38,-1000.97) 125.3,-1028.05 ccw(c90.6,-1062.75) 90.6,-1013.68 61.56,-1013.68
NetU49_3: U49.3 U52.5 | length 266.8
  Top Layer w10: U52.5@96.85,-812.4 cw(c96.85,-865.55) 150,-865.55 150,-962.5 ccw(c175.59,-962.5) 175.59,-988.09 U49.3@221.75,-988.09
NetU53_6: U53.6 U53.7 U55.3 | length 790.4
  Top Layer w10: U53.7@487.5,-1468.01 v3(487.5,-1422.5) ; U53.6@537.5,-1468.01 v3(537.5,-1422.5) ; U55.3@593.21,-950 v3(650,-950)
  Bottom Layer w10: v3(487.5,-1422.5) v3(537.5,-1422.5) 567.87,-1422.5 ccw(c567.87,-1302.87) 687.5,-1302.87 687.5,-987.5 ccw(c650,-987.5) v3(650,-950)
NetU56_4: U56.4 U58.14 | length 250.3
  Top Layer w10: U56.4@741.14,109.25 741.14,79.16 ccw(c766.26,79.16) 766.26,54.04 871.63,54.04 ccw(c871.63,79.06) 896.65,79.06 U58.14@896.65,115.16
NetU56_5: U56.5 U58.17 | length 394.2
  Top Layer w10: U56.5@715.55,109.25 715.55,71.77 ccw(c759.76,71.77) 759.76,27.56 846.54,27.56 cw(c846.54,-73.74) 947.83,-73.74 U58.17@947.83,-115.16
NetU56_6: U56.6 U58.16 | length 394.2
  Top Layer w10: U56.6@689.96,109.25 689.96,71.77 ccw(c759.76,71.77) 759.76,1.97 846.54,1.97 cw(c846.54,-73.74) 922.24,-73.74 U58.16@922.24,-115.16
NetU56_7: U56.7 U58.15 | length 394.2
  Top Layer w10: U56.7@664.37,109.25 664.37,71.77 ccw(c759.76,71.77) 759.76,-23.62 846.54,-23.62 cw(c846.54,-73.74) 896.65,-73.74 U58.15@896.65,-115.16
NetU57_5: U57.5 U58.28 | length 863.9
  Top Layer w10: v3(1229.33,-157.48) U58.28@1229.33,-115.16
  Int6 (SB) w10: v2(650,425) v3(1229.33,-157.48)
NetU82_18: U82.18 U82.23 | length 174
  Top Layer w10: U82.18@3045.25,-1159.84 v1(3068.75,-1159.84) ; U82.23@3045.25,-1061.42 v1(3068.75,-1061.42)
  Int5 (ST) w10: v1@3068.7,-1159.89 ccw(c3068.7,-1134.89) 3093.7,-1134.89 3093.7,-1086.46 ccw(c3068.7,-1086.46) 3069.15,-1061.47 cw(c3069.38,-1051.47) v1@3068.72,-1061.45
NetU83_18: U83.18 U83.23 | length 174.1
  Top Layer w10: U83.18@3045.25,127.66 v1(3068.75,127.66) ; U83.23@3045.25,226.08 v1(3068.75,226.08)
  Int5 (ST) w10: v1@3068.08,126.99 ccw(c3068.08,151.99) 3093.08,151.99 3093.08,200.41 ccw(c3068.08,200.41) 3070.25,225.32 cw(c3071.16,235.28) 3068.35,225.68 v1@3068.08,225.41
NetU89A_5: U89A.5 U93A.4 | length 133.1
  Bottom Layer w10: U93A.4@-1546.85,1224.9 -1500,1224.9 ccw(c-1500,1250) -1474.9,1250 U89A.5@-1474.9,1296.85
NetU89B_5: U89B.5 U93B.4 | length 133.1
  Bottom Layer w10: U93B.4@-1546.85,324.9 -1500,324.9 ccw(c-1500,350) -1474.9,350 U89B.5@-1474.9,396.85
NetU89C_5: U89C.5 U93C.4 | length 133.1
  Bottom Layer w10: U93C.4@-1546.85,-575.1 -1500,-575.1 ccw(c-1500,-550) -1474.9,-550 U89C.5@-1474.9,-503.15
NetU89D_5: U89D.5 U93D.4 | length 133.1
  Bottom Layer w10: U93D.4@-1546.85,-1475.1 -1500,-1475.1 ccw(c-1500,-1450) -1474.9,-1450 U89D.5@-1474.9,-1403.15
PCIE.PCIE_CLK_N: C284.2 U45.E6 | length 1999.6
  Top Layer w5: U45.E6@216.54,-255.91 v2(236.22,-236.22)
  Bottom Layer w4.2: -914.75,-1304.29 -914.45,-1304.59 cw(c-914.45,-1319.04) -900,-1319.04 C284.2@-900,-1324.41 ; 180.8,-275.59 181.1,-275.59 cw(c196.85,-275.59) 196.85,-259.84 205.09,-259.84 ccw(c205.09,-244.09) 220.84,-244.09 cw(c228.71,-244.09) 228.71,-236.22 v2(236.22,-236.22)
  Bottom Layer w5: -914.75,-1304.29 -914.75,-1016.6 cw(c-335.28,-1016.6) -335.28,-437.13 157.05,-437.13 ccw(c157.05,-413.39) 180.8,-413.39 180.8,-275.59
PCIE.PCIE_CLK_P: C285.2 U45.F6 | length 1999.6
  Top Layer w5: v2(196.85,-236.22) U45.F6@216.54,-216.54
  Bottom Layer w4.2: C285.2@-937.5,-1324.41 -937.5,-1319.04 cw(c-923.05,-1319.04) -923.05,-1304.59 -922.75,-1304.29 ; 172.8,-275.59 172.5,-275.59 cw(c196.85,-275.59) 196.85,-251.24 205.09,-251.24 ccw(c205.09,-244.09) 212.24,-244.09 ccw(c204.36,-244.09) 204.36,-236.22 v2(196.85,-236.22)
  Bottom Layer w5: -922.75,-1304.29 -922.75,-1016.6 cw(c-335.28,-1016.6) -335.28,-429.13 157.05,-429.13 ccw(c157.05,-413.39) 172.8,-413.39 172.8,-275.59
PCIE.PCIE_PERST: U45.A15 U88.3 | length 1561.3
  Top Layer w5: v2(-157.48,-393.7) U45.A15@-137.8,-413.39
  Bottom Layer w5: U88.3@-1025.1,-1296.85 -1025.1,-998.98 cw(c-400.13,-998.98) -400.13,-374.02 -177.17,-374.02 cw(c-177.17,-393.7) v2(-157.48,-393.7)
PCIE.PCIE_PWRGD: U45.T1 U70.5 U71.5 | length 2955.1
  Top Layer w5: v2(393.7,196.85) U45.T1@413.39,177.17
  Top Layer w16: U70.5@2245.56,-774.11 v4(2281.25,-774.11) ; U71.5@2245.56,-574.11 v16(2281.25,-574.11)
  Int5 (ST) w6: v2(393.7,196.85) 869.23,196.85 cw(c869.23,99.87) 937.81,168.44 1324.82,-218.57 cw(c1273.39,-270.01) 1346.13,-270.01 1346.13,-567.2 ccw(c1446.13,-567.2) 1375.42,-637.92 1620.71,-883.21 ccw(c1691.42,-812.5) 1691.42,-912.5 2162.2,-912.5 ccw(c2162.2,-793.45) 2281.25,-793.45 v4(2281.25,-774.11)
  Int6 (SB) w10: v4(2281.25,-774.11) cw(c2281.25,-755.36) 2262.5,-755.36 2262.5,-592.86 cw(c2281.25,-592.86) v16(2281.25,-574.11)
PCIE.PCIE_RX0_N: P2.B15 U45.B8 | length 3121.5
  Top Layer w5: P2.B15@-1173.15,-2385 -1173.15,-2322 ccw(c-1226.7,-2322) -1188.83,-2284.14 -1188.83,-2214.51 cw(c-1088.83,-2214.51) -1159.55,-2143.8 -901.59,-1885.84 ccw(c-977.95,-1809.47) -869.95,-1809.47 -869.95,-1028.11 cw(c-318.34,-1028.11) -318.34,-476.5 -39.5,-476.5 ccw(c-39.5,-433.07) 3.94,-433.07 3.94,-295.28 cw(c19.68,-295.28) 19.68,-279.53 137.8,-279.53 cw(c137.8,-295.28) 153.54,-295.28 153.54,-381.83 cw(c145.67,-381.83) 145.67,-389.7 cw(c145.67,-384.33) 140.3,-384.33 140.3,-380.05 ccw(c131.76,-380.05) U45.B8@137.8,-374.02
PCIE.PCIE_RX0_P: P2.B14 U45.A8 | length 3159.2
  Top Layer w5: P2.B14@-1212.52,-2385 -1212.52,-2322 cw(c-1158.97,-2322) -1196.83,-2284.14 -1196.83,-2214.51 cw(c-1088.83,-2214.51) -1165.2,-2138.14 -907.24,-1880.18 ccw(c-977.95,-1809.47) -877.95,-1809.47 -877.95,-1028.11 cw(c-318.34,-1028.11) -318.34,-468.5 -39.5,-468.5 ccw(c-39.5,-433.07) -4.06,-433.07 -4.06,-295.28 cw(c19.68,-295.28) 19.68,-271.53 137.8,-271.53 cw(c137.8,-295.28) 161.54,-295.28 161.54,-381.83 cw(c145.67,-381.83) 145.67,-397.7 ccw(c145.67,-403.07) 140.3,-403.07 140.3,-407.35 cw(c131.76,-407.35) U45.A8@137.8,-413.39
PCIE.PCIE_RX1_N: P2.B20 U45.D11 | length 2743.3
  Top Layer w5: P2.B20@-976.3,-2385 -976.3,-2322 ccw(c-1030.34,-2322) -992.13,-2283.8 -992.13,-2218.59 cw(c-892.13,-2218.59) -962.84,-2147.88 -811.03,-1996.07 ccw(c-887.4,-1919.71) -779.4,-1919.71 -779.4,-1051.61 cw(c-243.79,-1051.61) -243.79,-516 -39.5,-516 ccw(c-39.5,-433.07) 43.43,-433.07 43.43,-326.83 ccw(c27.56,-326.83) 27.56,-310.96 cw(c27.56,-305.59) 22.19,-305.59 22.19,-301.31 ccw(c13.65,-301.31) U45.D11@19.69,-295.28
PCIE.PCIE_RX1_P: P2.B19 U45.C11 | length 2730.6
  Top Layer w5: P2.B19@-1015.67,-2385 -1015.67,-2322 cw(c-962.6,-2322.01) -1000.13,-2284.48 -1000.13,-2218.59 cw(c-892.13,-2218.59) -968.49,-2142.22 -816.69,-1990.42 ccw(c-887.4,-1919.71) -787.4,-1919.71 -787.4,-1051.61 cw(c-243.79,-1051.61) -243.79,-508 -39.5,-508 ccw(c-39.5,-433.07) 35.43,-433.07 35.43,-326.83 ccw(c27.56,-326.83) 27.56,-318.96 ccw(c27.56,-324.33) 22.19,-324.33 22.19,-328.61 cw(c13.65,-328.61) U45.C11@19.69,-334.65
PCIE.PCIE_RX2_N: P2.B24 U45.B10 | length 2577.8
  Top Layer w5: P2.B24@-818.82,-2385 -818.82,-2322 ccw(c-872.37,-2322) -834.5,-2284.14 -834.5,-2234.19 cw(c-734.5,-2234.19) -805.21,-2163.48 -724.42,-2082.69 ccw(c-800.79,-2006.32) -692.79,-2006.32 -692.79,-1074.98 cw(c-173.18,-1074.98) -173.18,-555.37 -39.5,-555.37 ccw(c-39.5,-433.07) 82.8,-433.07 82.8,-405.57 ccw(c66.93,-405.57) 66.93,-389.7 cw(c66.93,-384.33) 61.56,-384.33 61.56,-380.05 ccw(c53.02,-380.05) U45.B10@59.06,-374.02
PCIE.PCIE_RX2_P: P2.B23 U45.A10 | length 2565.2
  Top Layer w5: P2.B23@-858.19,-2385 -858.19,-2322 cw(c-804.64,-2322) -842.5,-2284.14 -842.5,-2234.19 cw(c-734.5,-2234.19) -810.87,-2157.83 -730.08,-2077.03 ccw(c-800.79,-2006.32) -700.79,-2006.32 -700.79,-1074.98 cw(c-173.18,-1074.98) -173.18,-547.37 -39.5,-547.37 ccw(c-39.5,-433.07) 74.8,-433.07 74.8,-405.57 ccw(c66.93,-405.57) 66.93,-397.7 ccw(c66.93,-403.07) 61.56,-403.07 61.56,-407.35 cw(c53.02,-407.35) U45.A10@59.06,-413.39
PCIE.PCIE_RX3_N: P2.B28 U45.D9 | length 2572.7
  Top Layer w5: P2.B28@-661.34,-2385 -661.34,-2322 ccw(c-714.89,-2322) -677.02,-2284.14 -677.02,-2242.07 cw(c-577.02,-2242.07) -647.73,-2171.36 -633.86,-2157.48 ccw(c-700.7,-2090.64) -606.17,-2090.64 -606.17,-1098.22 cw(c-102.56,-1098.22) -102.56,-594.61 -33.95,-594.61 ccw(c-33.95,-438.61) 122.05,-438.61 122.05,-326.71 ccw(c106.3,-326.71) 106.3,-310.96 cw(c106.3,-305.59) 100.93,-305.59 100.93,-301.31 ccw(c92.39,-301.31) U45.D9@98.43,-295.28
PCIE.PCIE_RX3_P: P2.B27 U45.C9 | length 2560.2
  Top Layer w5: P2.B27@-700.71,-2385 -700.71,-2322 cw(c-647.16,-2322) -685.02,-2284.14 -685.02,-2242.07 cw(c-577.02,-2242.07) -653.39,-2165.7 -639.52,-2151.82 ccw(c-700.7,-2090.64) -614.17,-2090.64 -614.17,-1098.22 cw(c-102.56,-1098.22) -102.56,-586.61 -33.95,-586.61 ccw(c-33.95,-438.61) 114.05,-438.61 114.05,-326.71 ccw(c106.3,-326.71) 106.3,-318.96 ccw(c106.3,-324.33) 100.93,-324.33 100.93,-328.61 cw(c92.39,-328.61) U45.C9@98.43,-334.65
PCIE.PCIE_TX0_N: C280.2 U45.B4 | length 1894.4
  Top Layer w5: U45.B4@295.28,-374.02 v2(314.96,-393.7)
  Bottom Layer w5: C280.2@-812.5,-1324.41 -812.5,-1318.94 ccw(c-827.25,-1318.94) -827.25,-1304.19 -827.25,-1039.97 cw(c-263.78,-1039.97) -263.78,-476.5 314.96,-476.5 ccw(c314.96,-452.76) 338.71,-452.76 338.71,-425.26 ccw(c322.83,-425.26) 322.83,-409.39 cw(c322.83,-401.51) 314.96,-401.51 v2(314.96,-393.7)
PCIE.PCIE_TX0_P: C282.2 U45.A4 | length 1881.9
  Top Layer w5: U45.A4@295.28,-413.39 v2(314.96,-433.07)
  Bottom Layer w5: C282.2@-850,-1324.41 -850,-1318.94 cw(c-835.25,-1318.94) -835.25,-1304.19 -835.25,-1039.97 cw(c-263.78,-1039.97) -263.78,-468.5 314.96,-468.5 ccw(c314.96,-452.76) 330.71,-452.76 330.71,-425.26 ccw(c322.83,-425.26) 322.83,-417.39 ccw(c322.83,-425.26) 314.96,-425.26 v2(314.96,-433.07)
PCIE.PCIE_TX1_N: C278.2 U45.D5 | length 1976.9
  Top Layer w5: U45.D5@255.91,-295.28 v2(275.59,-314.96)
  Bottom Layer w5: C278.2@-725,-1324.41 -725,-1318.94 ccw(c-739.75,-1318.94) -739.75,-1304.19 -739.75,-1063.54 cw(c-192.28,-1063.54) -192.28,-516.07 314.96,-516.07 ccw(c314.96,-452.95) 378.08,-452.95 378.08,-393.7 ccw(c354.33,-393.7) 354.33,-369.95 314.83,-369.95 cw(c314.83,-354.46) 299.34,-354.46 299.34,-346.52 ccw(c283.46,-346.52) 283.46,-330.65 cw(c283.46,-322.77) 275.59,-322.77 v2(275.59,-314.96)
PCIE.PCIE_TX1_P: C279.2 U45.C5 | length 1964.4
  Top Layer w5: U45.C5@255.91,-334.65 v2(275.59,-354.33)
  Bottom Layer w5: C279.2@-762.5,-1324.41 -762.5,-1318.94 cw(c-747.75,-1318.94) -747.75,-1304.19 -747.75,-1063.54 cw(c-192.28,-1063.54) -192.28,-508.07 314.96,-508.07 ccw(c314.96,-452.95) 370.08,-452.95 370.08,-393.7 ccw(c354.33,-393.7) 354.33,-377.95 314.83,-377.95 cw(c314.83,-354.46) 291.34,-354.46 291.34,-346.52 ccw(c283.46,-346.52) 283.46,-338.65 ccw(c283.46,-346.52) 275.59,-346.52 v2(275.59,-354.33)
PCIE.PCIE_TX2_N: C276.2 U45.B6 | length 2138.2
  Top Layer w5: U45.B6@216.54,-374.02 v2(236.22,-393.7)
  Bottom Layer w5: C276.2@-637.5,-1324.41 -637.5,-1318.94 ccw(c-652.25,-1318.94) -652.25,-1304.19 -652.25,-1086.91 cw(c-120.78,-1086.91) -120.78,-555.44 314.96,-555.44 ccw(c314.96,-452.95) 417.45,-452.95 417.45,-354.33 ccw(c393.83,-354.33) 393.83,-330.71 354.4,-330.71 cw(c354.33,-315.09) 338.71,-315.12 ccw(c314.96,-314.96) 314.99,-291.21 275.59,-291.21 ccw(c275.59,-314.83) 251.97,-314.83 251.97,-401.51 cw(c244.09,-401.51) 244.09,-409.39 cw(c244.09,-401.51) 236.22,-401.51 v2(236.22,-393.7)
PCIE.PCIE_TX2_P: C277.2 U45.A6 | length 2125.6
  Top Layer w5: U45.A6@216.54,-413.39 v2(236.22,-433.07)
  Bottom Layer w5: C277.2@-675,-1324.41 -675,-1318.94 cw(c-660.25,-1318.94) -660.25,-1304.19 -660.25,-1086.91 cw(c-120.78,-1086.91) -120.78,-547.44 314.96,-547.44 ccw(c314.96,-452.95) 409.45,-452.95 409.45,-354.33 ccw(c393.83,-354.33) 393.83,-338.71 354.4,-338.71 cw(c354.33,-315.09) 330.71,-315.1 ccw(c314.96,-314.96) 314.99,-299.21 275.59,-299.21 ccw(c275.59,-314.83) 259.97,-314.83 259.97,-401.51 cw(c244.09,-401.51) 244.09,-417.39 ccw(c244.09,-425.26) 236.22,-425.26 v2(236.22,-433.07)
PCIE.PCIE_TX3_N: C274.2 U45.D7 | length 2143.3
  Top Layer w5: U45.D7@177.17,-295.28 v2(196.85,-314.96)
  Bottom Layer w5: C274.2@-550,-1324.41 -550,-1318.94 ccw(c-564.75,-1318.94) -564.75,-1304.19 -564.75,-1087.25 cw(c-72.31,-1087.25) -72.31,-594.81 314.96,-594.81 ccw(c314.96,-452.95) 456.82,-452.95 456.82,-334.65 ccw(c413.51,-334.65) 413.51,-291.34 393.7,-291.34 cw(c393.7,-275.72) 378.08,-275.72 378.08,-275.59 ccw(c354.33,-275.59) 354.33,-251.84 275.59,-251.84 ccw(c275.59,-314.83) 212.6,-314.83 212.6,-322.77 cw(c204.72,-322.77) 204.72,-330.65 cw(c204.72,-322.77) 196.85,-322.77 v2(196.85,-314.96)
PCIE.PCIE_TX3_P: C275.2 U45.C7 | length 2130.8
  Top Layer w5: U45.C7@177.17,-334.65 v2(196.85,-354.33)
  Bottom Layer w5: C275.2@-587.5,-1324.41 -587.5,-1318.94 cw(c-572.75,-1318.94) -572.75,-1304.19 -572.75,-1087.25 cw(c-72.31,-1087.25) -72.31,-586.81 314.96,-586.81 ccw(c314.96,-452.95) 448.82,-452.95 448.82,-334.65 ccw(c413.51,-334.65) 413.51,-299.34 393.7,-299.34 cw(c393.7,-275.72) 370.08,-275.72 370.08,-275.59 ccw(c354.33,-275.59) 354.33,-259.84 275.59,-259.84 ccw(c275.59,-314.83) 220.6,-314.83 220.6,-322.77 cw(c204.72,-322.77) 204.72,-338.65 ccw(c204.72,-346.52) 196.85,-346.52 v2(196.85,-354.33)
PER0_N: C280.1 P2.A17 | length 1137.8
  Bottom Layer w5: P2.A17@-1094.41,-2385 -1094.41,-2315.51 ccw(c-1110.09,-2315.51) -1110.09,-2299.82 -1110.09,-2234.02 cw(c-1010.09,-2234.02) -1080.81,-2163.31 -858.62,-1941.12 ccw(c-934.34,-1865.39) -827.25,-1865.39 -827.25,-1395.81 cw(c-822.25,-1395.81) -825.79,-1392.28 -824.32,-1390.81 ccw(c-824.32,-1389.5) -823.4,-1390.43 -815.28,-1382.31 ccw(c-822,-1375.59) C280.1@-812.5,-1375.59 C280.1@-812.5,-1381.06
PER0_P: C282.1 P2.A16 | length 1137.8
  Bottom Layer w5: P2.A16@-1133.78,-2385 -1133.78,-2315.51 cw(c-1118.09,-2315.51) -1118.09,-2299.82 -1118.09,-2234.02 cw(c-1010.09,-2234.02) -1086.46,-2157.65 -864.29,-1935.48 ccw(c-934.4,-1865.37) -835.25,-1865.37 -835.25,-1395.81 ccw(c-840.25,-1395.81) -836.71,-1392.28 -838.18,-1390.81 cw(c-838.18,-1389.5) -839.1,-1390.43 -847.22,-1382.31 cw(c-840.5,-1375.59) C282.1@-850,-1375.59 C282.1@-850,-1381.06
PER1_N: C278.1 P2.A22 | length 1089.7
  Bottom Layer w5: P2.A22@-897.56,-2385 -897.56,-2315.51 ccw(c-913.24,-2315.51) -913.24,-2299.82 -913.24,-2232.17 cw(c-813.24,-2232.17) -883.95,-2161.45 -771.38,-2048.88 ccw(c-847.75,-1972.51) -739.75,-1972.51 -739.75,-1395.81 ccw(c-739.75,-1381.06) -725,-1381.06 C278.1@-725,-1375.59
PER1_P: C279.1 P2.A21 | length 1089.7
  Bottom Layer w5: P2.A21@-936.93,-2385 -936.93,-2315.51 cw(c-921.24,-2315.51) -921.24,-2299.82 -921.24,-2232.17 cw(c-813.24,-2232.17) -889.61,-2155.8 -777.04,-2043.23 ccw(c-847.75,-1972.51) -747.75,-1972.51 -747.75,-1395.81 cw(c-747.75,-1381.06) -762.5,-1381.06 C279.1@-762.5,-1375.59
PER2_N: C276.1 P2.A26 | length 1060.7
  Bottom Layer w5: P2.A26@-740.08,-2385 -740.08,-2315.51 ccw(c-755.76,-2315.51) -755.76,-2299.82 -755.76,-2234.68 cw(c-655.76,-2234.68) -726.47,-2163.97 -683.88,-2121.38 ccw(c-760.25,-2045.01) -652.25,-2045.01 -652.25,-1395.81 ccw(c-652.25,-1381.06) -637.5,-1381.06 C276.1@-637.5,-1375.59
PER2_P: C277.1 P2.A25 | length 1060.7
  Bottom Layer w5: P2.A25@-779.45,-2385 -779.45,-2315.51 cw(c-763.76,-2315.51) -763.76,-2299.82 -763.76,-2234.68 cw(c-655.76,-2234.68) -732.13,-2158.32 -689.54,-2115.73 ccw(c-760.25,-2045.01) -660.25,-2045.01 -660.25,-1395.81 cw(c-660.25,-1381.06) -675,-1381.06 C277.1@-675,-1375.59
PER3_N: C274.1 P2.A30 | length 1038.4
  Bottom Layer w5: P2.A30@-582.6,-2385 -582.6,-2315.51 ccw(c-598.28,-2315.51) -598.28,-2299.82 -598.28,-2219.57 cw(c-552.93,-2219.57) -585,-2187.5 ccw(c-633.83,-2138.64) -564.75,-2138.64 -564.75,-1397.34 cw(c-556.06,-1397.34) -562.2,-1391.19 cw(c-561.28,-1392.11) -561.28,-1390.81 -552.78,-1382.31 ccw(c-559.5,-1375.59) C274.1@-550,-1375.59 C274.1@-550,-1381.06
PER3_P: C275.1 P2.A29 | length 1038.4
  Bottom Layer w5: P2.A29@-621.97,-2385 -621.97,-2315.51 cw(c-606.28,-2315.51) -606.28,-2299.82 -606.28,-2219.57 cw(c-552.93,-2219.57) -590.66,-2181.84 ccw(c-633.89,-2138.61) -572.75,-2138.61 -572.75,-1397.34 ccw(c-581.44,-1397.34) -575.3,-1391.19 ccw(c-576.22,-1392.11) -576.22,-1390.81 -584.72,-1382.31 cw(c-578,-1375.59) C275.1@-587.5,-1375.59 C275.1@-587.5,-1381.06
PERST#: P2.A11 R317.1 | length 982.8
  Bottom Layer w10: P2.A11@-1409.06,-2385 -1409.06,-2190.17 cw(c-1273.57,-2190.17) -1369.37,-2094.37 -1117.38,-1842.38 ccw(c-1188.09,-1771.67) -1088.09,-1771.67 R317.1@-1088.09,-1525
PG0: U45.U1 U74.5 | length 2815.3
  Top Layer w5: v2(393.7,236.22) U45.U1@413.39,216.54
  Int5 (ST) w6: v2(393.7,236.22) 869.23,236.22 cw(c869.23,99.87) 965.64,196.28 1355.29,-193.37 cw(c1282.38,-266.28) 1385.5,-266.28 1385.5,-344.07 ccw(c1485.5,-344.07) 1414.79,-414.79 1501.96,-501.96 ccw(c1572.67,-431.25) 1572.67,-531.25 2162.37,-531.25 ccw(c2162.37,-456.12) 2237.5,-456.12 2237.5,-17.86 cw(c2281.25,-17.86) v4(2281.25,25.89)
PG1: U45.V3 U75.5 | length 2379.9
  Top Layer w5: v2(314.96,275.59) U45.V3@334.65,255.91
  Int5 (ST) w5: v2(314.96,275.59) v2@320.73,269.82 ; v2@320.74,269.82 ccw(c354.33,303.43) 354.33,255.91 629.92,255.91 ccw(c629.92,446) 764.34,311.58 1109.39,656.64 cw(c1180.1,585.93) 1180.1,685.93 2174.07,685.93 cw(c2174.07,635) 2225,635 2225,482.14 ccw(c2281.25,482.14) v4(2281.25,425.89)
PG2: U45.U2 U72.5 | length 2754
  Top Layer w6: v2(354.33,236.22) U45.U2@374.02,216.54
  Int5 (ST) w6: v2(354.33,236.22) 360.1,230.46 ccw(c393.7,264.06) 393.7,216.54 869.23,216.54 cw(c869.23,99.87) 951.72,182.36 1341.37,-207.28 cw(c1282.38,-266.28) 1365.81,-266.28 1365.81,-380.64 ccw(c1465.81,-380.64) 1395.1,-451.35 1620.71,-676.96 ccw(c1691.42,-606.25) 1691.42,-706.25 2161.92,-706.25 ccw(c2161.92,-555.67) 2312.5,-555.67 2312.5,-405.36 ccw(c2281.25,-405.36) v4(2281.25,-374.11)
PG3: U45.Y2 U83.10 | length 3237.6
  Top Layer w5: U45.Y2@374.02,334.65 v2(393.7,354.33) ; v1@2868.75,68.6 v1(2868.75,68.75)
  Top Layer w10: v1@2868.75,68.6 U83.10@2892.25,68.6
  Int5 (ST) w5: v2(393.7,354.33) 468.5,354.33 629.92,354.33 ccw(c629.92,508.43) 738.89,399.47 1054.79,715.37 cw(c1181.17,588.98) 1181.17,767.72 2602.11,767.72 cw(c2602.11,667.72) 2672.82,738.43 2801.96,609.29 cw(c2731.25,538.58) 2831.25,538.58 2831.25,147.67 ccw(c2931.25,147.67) 2860.54,76.96 v1(2868.75,68.75)
PG4: U45.AA3 U83.3 | length 3213.6
  Top Layer w5: v2(314.96,393.7) U45.AA3@334.65,374.02
  Top Layer w10: v1(2868.75,206.4) U83.3@2892.25,206.4
  Int5 (ST) w5: v2(314.96,393.7) ccw(c362.48,441.22) 362.48,374.02 629.92,374.02 ccw(c629.92,508.43) 724.97,413.39 1040.87,729.29 cw(c1181.17,588.98) 1181.17,787.4 2602.11,787.4 cw(c2602.11,667.72) 2686.74,752.35 2815.88,623.21 cw(c2731.25,538.58) 2850.94,538.58 2850.94,224.21 ccw(c2868.75,224.21) v1(2868.75,206.4)
PG5: U45.AB1 U64.20 | length 1731
  Top Layer w5: v1(1754.53,1197.36) U64.20@1754.53,1215.16
  Top Layer w6: v2(393.7,433.07) U45.AB1@413.39,413.39
  Int5 (ST) w5: v2(393.7,433.07) 393.7,447.81 cw(c477.39,447.81) 477.39,531.5 738.91,531.5 ccw(c738.91,651.18) 823.54,566.55 1365.2,1108.21 cw(c1435.91,1037.5) 1435.91,1137.5 1653.24,1137.5 ccw(c1653.24,1237.5) 1723.96,1166.79 v1(1754.53,1197.36)
PG6: U45.W2 U82.3 | length 4245.2
  Top Layer w5: U45.W2@374.02,295.28 v2(393.7,314.96)
  Top Layer w10: v1(2868.75,-1081.1) U82.3@2892.25,-1081.1
  Int5 (ST) w5: v2(393.7,314.96) 629.92,314.96 ccw(c629.92,508.43) 766.73,371.63 1082.62,687.53 cw(c1181.17,588.98) 1181.17,728.35 2274.92,728.35 cw(c2274.92,608.66) 2359.55,693.29 2728.38,324.46 cw(c2643.75,239.83) 2763.44,239.83 2763.44,25.8 ccw(c2883.12,25.8) 2798.49,-58.83 2933.7,-194.03 cw(c2849.06,-278.66) 2968.75,-278.66 2968.75,-677.33 cw(c2850,-677.33) 2933.97,-761.3 2879.29,-815.98 ccw(c2950,-886.69) 2850,-886.69 2850,-1062.35 ccw(c2868.75,-1062.35) v1(2868.75,-1081.1)
PG7: U45.V2 U82.10 | length 4398.5
  Top Layer w6: v2(354.33,275.59) U45.V2@374.02,255.91
  Top Layer w10: v1(2868.75,-1218.9) U82.10@2892.25,-1218.9
  Int5 (ST) w5: v2(354.33,275.59) 360.09,281.35 cw(c393.7,247.75) 393.7,295.28 629.92,295.28 ccw(c629.92,508.43) 780.65,357.71 1096.55,673.61 cw(c1181.17,588.98) 1181.17,708.66 2274.92,708.66 cw(c2274.92,608.66) 2345.63,679.37 2714.46,310.54 cw(c2643.75,239.83) 2743.75,239.83 2743.75,25.8 ccw(c2883.12,25.8) 2784.57,-72.75 2920.71,-208.89 cw(c2850,-279.6) 2950,-279.6 2950,-677.33 cw(c2850,-677.33) 2920.71,-748.04 2866.03,-802.72 ccw(c2950,-886.69) 2831.25,-886.69 2831.25,-1139.98 ccw(c2931.25,-1139.98) 2860.54,-1210.69 v1(2868.75,-1218.9)
PG8: U45.R4 U67.4 | length 3340.7
  Top Layer w6: U45.R4@295.28,137.8 v2(314.96,157.48)
  Top Layer w16: U67.4@2245.56,-1399.7 v4(2281.25,-1399.7)
  Int5 (ST) w6: v2(314.96,157.48) ccw(c363.2,205.72) 363.2,137.5 634.02,137.5 cw(c634.02,37.5) 704.73,108.21 1080.31,-267.36 cw(c987.5,-360.17) 1118.75,-360.17 1118.75,-1192.33 ccw(c1218.75,-1192.33) 1148.04,-1263.04 1255.42,-1370.42 ccw(c1326.13,-1299.7) 1326.13,-1399.7 1780.78,-1399.7 cw(c1780.78,-1499.7) 1851.49,-1428.99 1936.96,-1514.46 ccw(c2007.67,-1443.75) 2007.67,-1543.75 2161.74,-1543.75 ccw(c2161.74,-1424.24) 2281.25,-1424.24 v4(2281.25,-1399.7)
PG9: U45.R2 U69.5 | length 2736.7
  Top Layer w5: U45.R2@374.02,137.8 v2(393.7,157.48)
  Int5 (ST) w6: v2(393.7,157.48) 658.24,157.48 cw(c658.24,57.48) 728.95,128.19 1102.4,-245.27 cw(c987.5,-360.17) 1150,-360.17 1150,-639.83 ccw(c1250,-639.83) 1179.29,-710.54 1551.96,-1083.21 ccw(c1622.67,-1012.5) 1622.67,-1112.5 2162.97,-1112.5 ccw(c2162.97,-994.22) 2281.25,-994.22 v4(2281.25,-974.11)
PG10: U45.R3 | length 27.8
  Top Layer w5: U45.R3@334.65,137.8 v2(354.33,157.48)
POWER.PWRSYNC: R252.2 TP26.1 U45.AB2 | length 2838.1
  Top Layer w5: v2(354.33,393.7) U45.AB2@374.02,413.39
  Int5 (ST) w5: v2(354.33,393.7) 348.57,399.47 cw(c382.17,433.07) 334.65,433.07 334.65,1100.31 cw(c434.65,1100.31) 363.94,1171.02 976.02,1783.1 cw(c1167.68,1591.47) 1167.68,1862.5 1717.91,1862.5 cw(c1717.91,1694.48) 1836.71,1813.29 TP26.1@1850,1800
  Bottom Layer w5: R252.2@1762.5,1588.09 1762.5,1617.61 cw(c1862.5,1617.61) 1791.79,1688.32 1820.71,1717.24 ccw(c1750,1787.95) 1850,1787.95 TP26.1@1850,1800
PROG: R304.1 U45.N12 | length 615.3
  Top Layer w5: v2(-39.37,78.74) U45.N12@-19.68,59.06
  Bottom Layer w5: R304.1@-216.54,505.91 -216.54,118.11 ccw(c-177.17,118.11) -177.17,78.74 v2(-39.37,78.74)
